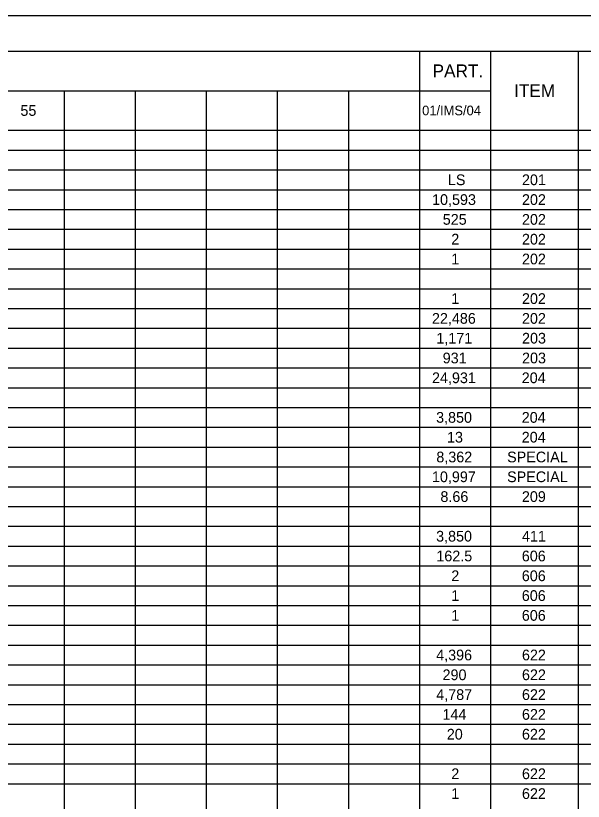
# Model space of a CAD drawing. Extents: x 0 to 34, y 0 to 22.
# Drawn here: x 8.85 to 16.87, y 10.89 to 22 of the extents above; entities that cross this region are included whole.
import ezdxf

# ---------------------------------------------------------------- set-up
doc = ezdxf.new("R2010")
doc.units = 0
for name, color, linetype in [('Default', 7, 'Continuous'), ('SH_Border', 7, 'Continuous'), ('SH_Cut_Line', 7, 'Continuous')]:
    doc.layers.add(name, color=color, linetype=linetype)

msp = doc.modelspace()

# ---------------------------------------------------------------- linework, layer by layer
at = {"layer": 'Default'}
for p, q in [((1.5, 21.5), (32, 21.5)), ((14.56, 21.5), (14.56, 0.5)), ((15.564, 21.5), (15.564, 0.5)), ((16.799, 21.5), (16.799, 0.5)), ((1.5, 20.94), (15.564, 20.94)), ((9.537, 20.94), (9.537, 0.5)), ((10.541, 20.94), (10.541, 0.5)), ((11.546, 20.94), (11.546, 0.5)), ((12.55, 20.94), (12.55, 0.5)), ((13.555, 20.94), (13.555, 0.5)), ((1.5, 20.38), (32, 20.38)), ((1.5, 20.1), (32, 20.1)), ((1.5, 19.82), (32, 19.82)), ((1.5, 19.54), (32, 19.54)), ((1.5, 19.26), (32, 19.26)), ((1.5, 18.98), (32, 18.98)), ((1.5, 18.7), (32, 18.7)), ((1.5, 18.42), (32, 18.42)), ((1.5, 18.14), (32, 18.14)), ((1.5, 17.86), (32, 17.86)), ((1.5, 17.58), (32, 17.58)), ((1.5, 17.3), (32, 17.3)), ((1.5, 17.02), (32, 17.02)), ((1.5, 16.74), (32, 16.74)), ((1.5, 16.46), (32, 16.46)), ((1.5, 16.18), (32, 16.18)), ((1.5, 15.9), (32, 15.9)), ((1.5, 15.62), (32, 15.62)), ((1.5, 15.34), (32, 15.34)), ((1.5, 15.06), (32, 15.06)), ((1.5, 14.78), (32, 14.78)), ((1.5, 14.5), (32, 14.5)), ((1.5, 14.22), (32, 14.22)), ((1.5, 13.94), (32, 13.94)), ((1.5, 13.66), (32, 13.66)), ((1.5, 13.38), (32, 13.38)), ((1.5, 13.1), (32, 13.1)), ((1.5, 12.82), (32, 12.82)), ((1.5, 12.54), (32, 12.54)), ((1.5, 12.26), (32, 12.26)), ((1.5, 11.98), (32, 11.98)), ((1.5, 11.7), (32, 11.7)), ((1.5, 11.42), (32, 11.42)), ((1.5, 11.14), (32, 11.14))]:
    msp.add_line(p, q, dxfattribs=at)
at = {"layer": 'SH_Border'}
msp.add_lwpolyline([(1.5, 21.5), (33.5, 21.5), (33.5, 0.5), (1.5, 0.5)], close=True, dxfattribs=at)
at = {"layer": 'SH_Cut_Line'}
msp.add_lwpolyline([(0, 0), (34, 0), (34, 22), (0, 22)], close=True, dxfattribs=at)

# ---------------------------------------------------------------- texts
at = {"layer": 'Default'}
for s, height, p in [('PART.', 0.1818, (14.744, 21.129)), ('ITEM', 0.1818, (15.896, 20.849)), ('55', 0.1515, (8.92, 20.584)), ('01/IMS/04', 0.1364, (14.596, 20.592)), ('LS', 0.1515, (14.961, 19.604)), ('201', 0.1515, (16.007, 19.604)), ('10,593', 0.1515, (14.737, 19.324)), ('202', 0.1515, (16.007, 19.324)), ('525', 0.1515, (14.888, 19.044)), ('202', 0.1515, (16.007, 19.044)), ('2', 0.152, (15.008, 18.764)), ('202', 0.1515, (16.007, 18.764)), ('1', 0.152, (15.008, 18.484)), ('202', 0.1515, (16.007, 18.484)), ('1', 0.152, (15.008, 17.924)), ('202', 0.1515, (16.007, 17.924)), ('22,486', 0.1515, (14.735, 17.644)), ('202', 0.1515, (16.007, 17.644)), ('1,171', 0.1515, (14.797, 17.364)), ('203', 0.1515, (16.008, 17.364)), ('931', 0.1515, (14.887, 17.084)), ('203', 0.1515, (16.008, 17.084)), ('24,931', 0.1515, (14.736, 16.804)), ('204', 0.1515, (16.004, 16.804)), ('3,850', 0.1515, (14.794, 16.244)), ('204', 0.1515, (16.004, 16.244)), ('13', 0.1515, (14.948, 15.964)), ('204', 0.1515, (16.004, 15.964)), ('8,362', 0.1515, (14.797, 15.684)), ('SPECIAL', 0.1515, (15.797, 15.684)), ('10,997', 0.1515, (14.735, 15.404)), ('SPECIAL', 0.1515, (15.797, 15.404)), ('8.66', 0.1515, (14.855, 15.124)), ('209', 0.1515, (16.006, 15.124)), ('3,850', 0.1515, (14.794, 14.564)), ('411', 0.1515, (16.007, 14.564)), ('162.5', 0.1515, (14.797, 14.284)), ('606', 0.1515, (16.005, 14.284)), ('2', 0.152, (15.008, 14.004)), ('606', 0.1515, (16.005, 14.004)), ('1', 0.152, (15.008, 13.724)), ('606', 0.1515, (16.005, 13.724)), ('1', 0.152, (15.008, 13.444)), ('606', 0.1515, (16.005, 13.444)), ('4,396', 0.1515, (14.795, 12.884)), ('622', 0.1515, (16.007, 12.884)), ('290', 0.1515, (14.885, 12.604)), ('622', 0.1515, (16.007, 12.604)), ('4,787', 0.1515, (14.796, 12.324)), ('622', 0.1515, (16.007, 12.324)), ('144', 0.1515, (14.884, 12.044)), ('622', 0.1515, (16.007, 12.044)), ('20', 0.1515, (14.945, 11.764)), ('622', 0.1515, (16.007, 11.764)), ('2', 0.152, (15.008, 11.204)), ('622', 0.1515, (16.007, 11.204)), ('1', 0.152, (15.008, 10.924)), ('622', 0.1515, (16.007, 10.924))]:
    msp.add_text(s, height=height, dxfattribs=at).set_placement(p)

doc.saveas('drawing.dxf')
